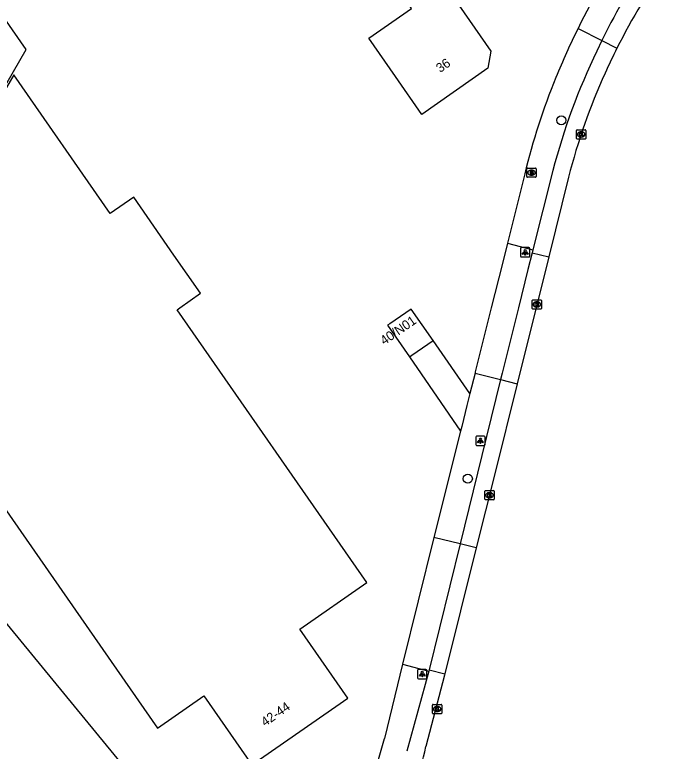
# Model space of a CAD drawing. Extents: x 156651 to 158072, y 387631 to 388990.
# Drawn here: x 157362.3 to 157432.6, y 387702.3 to 387781.5 of the extents above; entities that cross this region are included whole.
import ezdxf

# ---------------------------------------------------------------- set-up
doc = ezdxf.new("R2010")
doc.units = 0
for name, color, linetype in [('IMGEO_Boom', 7, 'Continuous'), ('IMGEO_Brandkraan', 7, 'Continuous'), ('IMGEO_Kolk', 7, 'Continuous'), ('IMGEO_Lichtpunt', 7, 'Continuous'), ('IMGEO_Pand', 7, 'Continuous'), ('IMGEO_Pand_nummerreeks', 7, 'Continuous'), ('IMGEO_Rijbaan_lokaal_open', 7, 'Continuous'), ('IMGEO_Voetpad_open', 7, 'Continuous')]:
    doc.layers.add(name, color=color, linetype=linetype)

msp = doc.modelspace()

# ---------------------------------------------------------------- linework, layer by layer
at = {"layer": 'IMGEO_Boom'}
for centre in [(157421.109, 387770.17), (157411.048, 387731.612)]:
    msp.add_circle(centre, 0.489, dxfattribs=at)
at = {"layer": 'IMGEO_Brandkraan'}
for p, q in [((157417.393, 387764.112), (157417.393, 387764.964)), ((157417.468, 387765.038), (157418.32, 387765.038)), ((157418.394, 387764.964), (157418.394, 387764.112)), ((157417.904, 387764.258), (157417.879, 387764.258)), ((157417.881, 387764.818), (157417.906, 387764.818)), ((157418.32, 387764.038), (157417.468, 387764.038))]:
    msp.add_line(p, q, dxfattribs=at)
for points in [[(157417.393, 387764.112), (157417.393, 387764.964)], [(157417.468, 387765.038), (157418.32, 387765.038)], [(157418.394, 387764.964), (157418.394, 387764.112)], [(157417.741, 387764.738), (157417.741, 387764.338), (157417.954, 387764.338)], [(157417.972, 387764.738), (157417.741, 387764.738)], [(157417.92, 387764.657), (157417.866, 387764.657), (157417.866, 387764.581)], [(157417.866, 387764.581), (157417.919, 387764.581)], [(157417.928, 387764.505), (157417.866, 387764.505), (157417.866, 387764.424)], [(157417.866, 387764.424), (157417.928, 387764.424)], [(157418.32, 387764.038), (157417.468, 387764.038)]]:
    msp.add_lwpolyline(points, dxfattribs=at)
for centre, radius, start, end in [((157417.47, 387764.962), 0.0765, 91.55205, 178.44795), ((157417.47, 387764.962), 0.0765, 91.55205, 178.44795), ((157418.318, 387764.962), 0.0765, 1.55205, 88.44795), ((157418.318, 387764.962), 0.0765, 1.55205, 88.44795), ((157417.47, 387764.114), 0.0765, 181.55205, 268.44795), ((157417.47, 387764.114), 0.0765, 181.55205, 268.44795), ((157417.921, 387764.619), 0.0379, 267.82845, 90.93552), ((157417.929, 387764.464), 0.0404, 269.87594, 90.50774), ((157417.96, 387764.589), 0.251, 268.66757, 293.53466), ((157417.976, 387764.593), 0.145, 59.4692, 91.53667), ((157418.001, 387764.64), 0.0922, 285.51372, 58.15012), ((157418.006, 387764.448), 0.105, 301.31148, 78.98903), ((157418.318, 387764.114), 0.0765, 271.55205, 358.44795), ((157418.318, 387764.114), 0.0765, 271.55205, 358.44795)]:
    msp.add_arc(centre, radius, start, end, dxfattribs=at)
for centre, major_axis, ratio, start_param, end_param in [((157417.88, 387764.538), (-0.387, 0.002), 0.722429, 4.712389, 7.853982), ((157417.905, 387764.538), (-0.39, 0.002), 0.717154, 1.570796, 4.712389)]:
    msp.add_ellipse(centre, major_axis=major_axis, ratio=ratio, start_param=start_param, end_param=end_param, dxfattribs=at)
at = {"layer": 'IMGEO_Kolk'}
for p, q in [((157422.739, 387768.225), (157422.739, 387769.077)), ((157422.814, 387769.151), (157423.666, 387769.151)), ((157423.227, 387768.931), (157423.252, 387768.931)), ((157423.74, 387769.077), (157423.74, 387768.225)), ((157423.666, 387768.151), (157422.814, 387768.151)), ((157423.25, 387768.371), (157423.225, 387768.371)), ((157417.977, 387749.933), (157417.977, 387750.785)), ((157418.052, 387750.859), (157418.904, 387750.859)), ((157418.465, 387750.639), (157418.49, 387750.639)), ((157418.978, 387750.785), (157418.978, 387749.933)), ((157418.904, 387749.859), (157418.052, 387749.859)), ((157418.488, 387750.079), (157418.463, 387750.079)), ((157412.889, 387729.416), (157412.889, 387730.268)), ((157412.964, 387730.342), (157413.816, 387730.342)), ((157413.377, 387730.122), (157413.402, 387730.122)), ((157413.89, 387730.268), (157413.89, 387729.416)), ((157413.816, 387729.342), (157412.964, 387729.342)), ((157413.4, 387729.562), (157413.375, 387729.562)), ((157407.244, 387706.412), (157407.244, 387707.264)), ((157407.319, 387707.338), (157408.171, 387707.338)), ((157407.732, 387707.118), (157407.757, 387707.118)), ((157408.245, 387707.264), (157408.245, 387706.412)), ((157408.171, 387706.338), (157407.319, 387706.338)), ((157407.755, 387706.558), (157407.73, 387706.558))]:
    msp.add_line(p, q, dxfattribs=at)
for points in [[(157422.739, 387768.225), (157422.739, 387769.077)], [(157422.814, 387769.151), (157423.666, 387769.151)], [(157423.06, 387768.851), (157423.183, 387768.851), (157423.183, 387768.7), (157423.313, 387768.851), (157423.477, 387768.851), (157423.331, 387768.7), (157423.484, 387768.451), (157423.332, 387768.451), (157423.247, 387768.615), (157423.183, 387768.548), (157423.183, 387768.451), (157423.06, 387768.451), (157423.06, 387768.851)], [(157423.74, 387769.077), (157423.74, 387768.225)], [(157423.666, 387768.151), (157422.814, 387768.151)], [(157417.977, 387749.933), (157417.977, 387750.785)], [(157418.052, 387750.859), (157418.904, 387750.859)], [(157418.978, 387750.785), (157418.978, 387749.933)], [(157418.904, 387749.859), (157418.052, 387749.859)], [(157418.298, 387750.559), (157418.421, 387750.559), (157418.421, 387750.408), (157418.551, 387750.559), (157418.715, 387750.559), (157418.569, 387750.408), (157418.722, 387750.159), (157418.57, 387750.159), (157418.485, 387750.323), (157418.421, 387750.256), (157418.421, 387750.159), (157418.298, 387750.159), (157418.298, 387750.559)], [(157412.889, 387729.416), (157412.889, 387730.268)], [(157412.964, 387730.342), (157413.816, 387730.342)], [(157413.21, 387730.042), (157413.333, 387730.042), (157413.333, 387729.891), (157413.463, 387730.042), (157413.627, 387730.042), (157413.481, 387729.891), (157413.634, 387729.642), (157413.482, 387729.642), (157413.397, 387729.806), (157413.333, 387729.739), (157413.333, 387729.642), (157413.21, 387729.642), (157413.21, 387730.042)], [(157413.89, 387730.268), (157413.89, 387729.416)], [(157413.816, 387729.342), (157412.964, 387729.342)], [(157407.244, 387706.412), (157407.244, 387707.264)], [(157407.319, 387707.338), (157408.171, 387707.338)], [(157408.245, 387707.264), (157408.245, 387706.412)], [(157408.171, 387706.338), (157407.319, 387706.338)], [(157407.565, 387707.038), (157407.688, 387707.038), (157407.688, 387706.887), (157407.818, 387707.038), (157407.982, 387707.038), (157407.836, 387706.887), (157407.989, 387706.638), (157407.837, 387706.638), (157407.752, 387706.802), (157407.688, 387706.735), (157407.688, 387706.638), (157407.565, 387706.638), (157407.565, 387707.038)]]:
    msp.add_lwpolyline(points, dxfattribs=at)
for centre, start, end in [((157422.816, 387769.075), 91.55205, 178.44795), ((157422.816, 387769.075), 91.55205, 178.44795), ((157423.664, 387769.075), 1.55205, 88.44795), ((157423.664, 387769.075), 1.55205, 88.44795), ((157422.816, 387768.227), 181.55205, 268.44795), ((157422.816, 387768.227), 181.55205, 268.44795), ((157423.664, 387768.227), 271.55205, 358.44795), ((157423.664, 387768.227), 271.55205, 358.44795), ((157418.054, 387750.783), 91.55205, 178.44795), ((157418.054, 387750.783), 91.55205, 178.44795), ((157418.902, 387750.783), 1.55205, 88.44795), ((157418.902, 387750.783), 1.55205, 88.44795), ((157418.054, 387749.935), 181.55205, 268.44795), ((157418.054, 387749.935), 181.55205, 268.44795), ((157418.902, 387749.935), 271.55205, 358.44795), ((157418.902, 387749.935), 271.55205, 358.44795), ((157412.966, 387730.266), 91.55205, 178.44795), ((157412.966, 387730.266), 91.55205, 178.44795), ((157413.814, 387730.266), 1.55205, 88.44795), ((157413.814, 387730.266), 1.55205, 88.44795), ((157412.966, 387729.418), 181.55205, 268.44795), ((157412.966, 387729.418), 181.55205, 268.44795), ((157413.814, 387729.418), 271.55205, 358.44795), ((157413.814, 387729.418), 271.55205, 358.44795), ((157407.321, 387707.262), 91.55205, 178.44795), ((157407.321, 387707.262), 91.55205, 178.44795), ((157408.169, 387707.262), 1.55205, 88.44795), ((157408.169, 387707.262), 1.55205, 88.44795), ((157407.321, 387706.414), 181.55205, 268.44795), ((157407.321, 387706.414), 181.55205, 268.44795), ((157408.169, 387706.414), 271.55205, 358.44795), ((157408.169, 387706.414), 271.55205, 358.44795)]:
    msp.add_arc(centre, 0.0765, start, end, dxfattribs=at)
for centre, major_axis, ratio, start_param, end_param in [((157423.226, 387768.651), (-0.387, 0.002), 0.722429, 4.712389, 7.853982), ((157423.251, 387768.651), (-0.39, 0.002), 0.717154, 1.570796, 4.712389), ((157418.464, 387750.359), (-0.387, 0.002), 0.722429, 4.712389, 7.853982), ((157418.489, 387750.359), (-0.39, 0.002), 0.717154, 1.570796, 4.712389), ((157413.376, 387729.842), (-0.387, 0.002), 0.722429, 4.712389, 7.853982), ((157413.401, 387729.842), (-0.39, 0.002), 0.717154, 1.570796, 4.712389), ((157407.731, 387706.838), (-0.387, 0.002), 0.722429, 4.712389, 7.853982), ((157407.756, 387706.838), (-0.39, 0.002), 0.717154, 1.570796, 4.712389)]:
    msp.add_ellipse(centre, major_axis=major_axis, ratio=ratio, start_param=start_param, end_param=end_param, dxfattribs=at)
at = {"layer": 'IMGEO_Lichtpunt'}
for p, q in [((157416.724, 387756.375), (157416.724, 387755.568)), ((157416.724, 387756.375), (157416.724, 387755.568)), ((157417.626, 387756.47), (157416.818, 387756.47)), ((157417.626, 387756.47), (157416.818, 387756.47)), ((157417.72, 387755.568), (157417.72, 387756.375)), ((157417.72, 387755.568), (157417.72, 387756.375)), ((157416.818, 387755.474), (157417.626, 387755.474)), ((157416.818, 387755.474), (157417.626, 387755.474)), ((157411.907, 387736.094), (157411.907, 387735.287)), ((157411.907, 387736.094), (157411.907, 387735.287)), ((157412.809, 387736.189), (157412.001, 387736.189)), ((157412.809, 387736.189), (157412.001, 387736.189)), ((157412.903, 387735.287), (157412.903, 387736.094)), ((157412.903, 387735.287), (157412.903, 387736.094)), ((157412.001, 387735.193), (157412.809, 387735.193)), ((157412.001, 387735.193), (157412.809, 387735.193)), ((157405.647, 387711.007), (157405.647, 387710.2)), ((157405.647, 387711.007), (157405.647, 387710.2)), ((157406.549, 387711.102), (157405.741, 387711.102)), ((157406.549, 387711.102), (157405.741, 387711.102)), ((157406.643, 387710.2), (157406.643, 387711.007)), ((157406.643, 387710.2), (157406.643, 387711.007)), ((157405.741, 387710.106), (157406.549, 387710.106)), ((157405.741, 387710.106), (157406.549, 387710.106))]:
    msp.add_line(p, q, dxfattribs=at)
for points in [[(157417.098, 387756.039), (157417.137, 387756.011), (157416.949, 387755.749), (157416.911, 387755.776), (157417.098, 387756.039)], [(157417.2, 387755.991), (157417.247, 387755.991), (157417.247, 387755.669), (157417.2, 387755.669), (157417.2, 387755.991)], [(157417.31, 387756.011), (157417.348, 387756.038), (157417.535, 387755.776), (157417.496, 387755.748), (157417.31, 387756.011)], [(157412.281, 387735.758), (157412.32, 387735.73), (157412.132, 387735.468), (157412.094, 387735.495), (157412.281, 387735.758)], [(157412.383, 387735.71), (157412.43, 387735.71), (157412.43, 387735.388), (157412.383, 387735.388), (157412.383, 387735.71)], [(157412.493, 387735.73), (157412.531, 387735.757), (157412.718, 387735.495), (157412.679, 387735.467), (157412.493, 387735.73)], [(157406.021, 387710.671), (157406.06, 387710.643), (157405.872, 387710.381), (157405.834, 387710.408), (157406.021, 387710.671)], [(157406.123, 387710.623), (157406.17, 387710.623), (157406.17, 387710.301), (157406.123, 387710.301), (157406.123, 387710.623)], [(157406.233, 387710.643), (157406.271, 387710.67), (157406.458, 387710.408), (157406.419, 387710.38), (157406.233, 387710.643)]]:
    msp.add_lwpolyline(points, dxfattribs=at)
for centre in [(157417.223, 387756.173), (157412.406, 387735.892), (157406.146, 387710.805)]:
    msp.add_circle(centre, 0.0994, dxfattribs=at)
for centre, start, end in [((157416.818, 387756.375), 90, 180), ((157416.818, 387756.375), 90, 180), ((157417.626, 387756.375), 0, 90), ((157417.626, 387756.375), 0, 90), ((157416.818, 387755.568), 180, 270), ((157416.818, 387755.568), 180, 270), ((157417.626, 387755.568), 270, 0), ((157417.626, 387755.568), 270, 360), ((157412.001, 387736.094), 90, 180), ((157412.001, 387736.094), 90, 180), ((157412.809, 387736.094), 0, 90), ((157412.809, 387736.094), 0, 90), ((157412.001, 387735.287), 180, 270), ((157412.001, 387735.287), 180, 270), ((157412.809, 387735.287), 270, 0), ((157412.809, 387735.287), 270, 360), ((157405.741, 387711.007), 90, 180), ((157405.741, 387711.007), 90, 180), ((157406.549, 387711.007), 0, 90), ((157406.549, 387711.007), 0, 90), ((157405.741, 387710.2), 180, 270), ((157405.741, 387710.2), 180, 270), ((157406.549, 387710.2), 270, 0), ((157406.549, 387710.2), 270, 360)]:
    msp.add_arc(centre, 0.0946, start, end, dxfattribs=at)
at = {"layer": 'IMGEO_Pand'}
for points in [[(157336.718, 387816.356), (157336.59, 387816.266), (157329.304, 387826.757), (157325.523, 387832.18), (157322.937, 387825.336), (157323.754, 387824.051), (157321.059, 387817.16), (157318.792, 387815.594), (157324.263, 387807.695), (157314.541, 387800.934), (157317.395, 387796.828), (157348.61, 387751.927), (157363.539, 387777.795), (157339.573, 387812.251), (157336.718, 387816.356)], [(157410.793, 387783.054), (157410.087, 387782.566), (157413.534, 387777.61), (157413.195, 387775.767), (157406.113, 387770.789), (157403.256, 387774.893), (157400.401, 387778.992), (157404.98, 387782.181), (157399.973, 387789.528), (157397.16, 387793.568)], [(157377.657, 387704.772), (157382.652, 387708.272), (157387.828, 387700.834), (157398.157, 387708.001), (157392.985, 387715.445), (157400.188, 387720.458), (157379.778, 387749.798), (157380.064, 387750), (157382.282, 387751.568), (157379.431, 387755.676), (157375.106, 387761.905), (157372.57, 387760.157), (157362.197, 387775.069), (157349.501, 387753.181), (157347.656, 387750), (157346.992, 387748.855), (157377.657, 387704.772)], [(157407.315, 387746.499), (157404.971, 387749.862), (157402.671, 387748.286), (157402.425, 387748.118), (157404.761, 387744.721)], [(157404.761, 387744.721), (157405.031, 387744.909), (157407.315, 387746.499)], [(157319.361, 387723.831), (157343.568, 387694.292), (157342.053, 387693.048), (157358.146, 387673.452), (157364.016, 387678.262), (157361.772, 387681), (157378.748, 387694.956), (157340.665, 387741.338)]]:
    msp.add_lwpolyline(points, dxfattribs=at)
at = {"layer": 'IMGEO_Rijbaan_lokaal_open'}
for points in [[(157421.883, 387764.06), (157419.75, 387755.49)], [(157419.75, 387755.49), (157416.352, 387741.837)], [(157416.352, 387741.837), (157413.943, 387732.158), (157411.953, 387724.164)], [(157411.953, 387724.164), (157408.587, 387710.639)], [(157408.587, 387710.639), (157408.546, 387710.475), (157406.549, 387702.827)]]:
    msp.add_lwpolyline(points, dxfattribs=at)
for centre, radius, start, end in [((157492.226, 387745.235), 72.872, 144.88662, 153.34674), ((157491.994, 387745.33), 72.622, 153.3321, 155.67655), ((157489.138, 387746.67), 69.467, 155.71354, 165.50291), ((157350.004, 387716.066), 58.074, 337.53729, 346.82244)]:
    msp.add_arc(centre, radius, start, end, dxfattribs=at)
at = {"layer": 'IMGEO_Voetpad_open'}
for points in [[(157422.907, 387780.061), (157425.468, 387778.755)], [(157425.468, 387778.755), (157424.931, 387777.616)], [(157425.564, 387778.958), (157425.468, 387778.755)], [(157425.468, 387778.755), (157427.098, 387777.924)], [(157417.181, 387764.402), (157415.317, 387756.937)], [(157420.199, 387764.779), (157418.062, 387756.254)], [(157415.317, 387756.937), (157414.778, 387754.777), (157413.568, 387750), (157411.825, 387743.116), (157411.822, 387742.953)], [(157415.317, 387756.937), (157418.062, 387756.254)], [(157418.062, 387756.254), (157417.981, 387755.931)], [(157417.981, 387755.931), (157417.524, 387754.106), (157416.495, 387750), (157414.737, 387742.983), (157414.565, 387742.282)], [(157417.981, 387755.931), (157419.75, 387755.49)], [(157411.26, 387740.768), (157407.315, 387746.499)], [(157404.761, 387744.721), (157410.265, 387736.718)], [(157411.822, 387742.953), (157411.26, 387740.768)], [(157411.822, 387742.953), (157414.565, 387742.282)], [(157414.565, 387742.282), (157412.565, 387734.129), (157410.226, 387724.594)], [(157414.565, 387742.282), (157416.352, 387741.837)], [(157411.26, 387740.768), (157410.951, 387739.482), (157410.394, 387737.236), (157410.265, 387736.718)], [(157410.265, 387736.718), (157407.41, 387725.277)], [(157407.41, 387725.277), (157404.025, 387711.652)], [(157410.226, 387724.594), (157407.41, 387725.277)], [(157410.226, 387724.594), (157406.879, 387711.062)], [(157411.953, 387724.164), (157410.226, 387724.594)], [(157404.025, 387711.652), (157402.071, 387703.678)], [(157404.025, 387711.652), (157406.843, 387710.916)], [(157406.879, 387711.062), (157406.843, 387710.916)], [(157406.879, 387711.062), (157408.587, 387710.639)], [(157406.843, 387710.916), (157404.504, 387702.298)]]:
    msp.add_lwpolyline(points, dxfattribs=at)
for centre, radius, start, end in [((157487.497, 387747.862), 72.171, 144.69918, 153.5028), ((157478.381, 387753.215), 58.757, 143.98023, 154.01577), ((157487.628, 387747.77), 72.329, 153.48419, 158.08372), ((157488.653, 387746.836), 70.766, 154.21778, 165.31223), ((157486.056, 387747.897), 70.825, 157.70426, 166.52381), ((157363.356, 387713.183), 39.865, 334.25284, 346.20551)]:
    msp.add_arc(centre, radius, start, end, dxfattribs=at)

# ---------------------------------------------------------------- texts
at = {"layer": 'IMGEO_Pand_nummerreeks'}
for s, rotation, p in [('36', 35.10512, (157408.072, 387775.247)), ('40/N01', 34.55508, (157402.052, 387745.948)), ('42-44', 34.8301, (157389.23, 387704.914))]:
    msp.add_text(s, height=1, rotation=rotation, dxfattribs=at).set_placement(p)

doc.saveas('drawing.dxf')
